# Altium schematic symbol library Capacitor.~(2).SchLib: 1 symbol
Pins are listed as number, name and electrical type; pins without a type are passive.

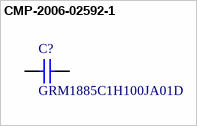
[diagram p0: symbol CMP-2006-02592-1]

## CMP-2006-02592-1
designator C?, comment GRM1885C1H100JA01D
Manufacturer: Murata
footprint CAPC1608X90X35ML10T15 (Chip Capacitor, 2-Leads, Body 1.60x0.80mm, IPC Low Density)
footprint CAPC1608X90X35LL10T15 (Chip Capacitor, 2-Leads, Body 1.60x0.80mm, IPC High Density)
footprint CAPC1608X90X35NL10T15 (Chip Capacitor, 2-Leads, Body 1.60x0.80mm, IPC Medium Density)
pins: 1, 2
1 alternate drawing of the same symbol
